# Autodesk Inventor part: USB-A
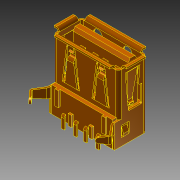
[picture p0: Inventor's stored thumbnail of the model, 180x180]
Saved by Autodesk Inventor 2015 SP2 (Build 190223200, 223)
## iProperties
Created: 2015-08
Part Number: USB-A
Material: Kupfer
Document SubType Name: Modeling
Designer: rYan
Density: 8.94 g/cm^3
Appearance: Kupfer - satiniert
Author: workeradm
Title: c-292303-7-d-3d.igs
Organization: Unknown
Description: PTC IGES file: c-292303-7-d-3d.igs
Sending System: Pro/ENGINEER by Parametric Technology Corporation
Preprocessor: 2009300
Minimum Resolution: 0.002491
Sending System Product ID: C-292303-7
Receiving System Product ID: C-292303-7
Sent Units: Millimeter
Translation Standard: USPRO/IPO100 IGES 5.2
Author: rYan
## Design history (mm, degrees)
node "c-292303-7-d-3d1"
feature "Zusammengesetzt1"
node "Fläche1"
